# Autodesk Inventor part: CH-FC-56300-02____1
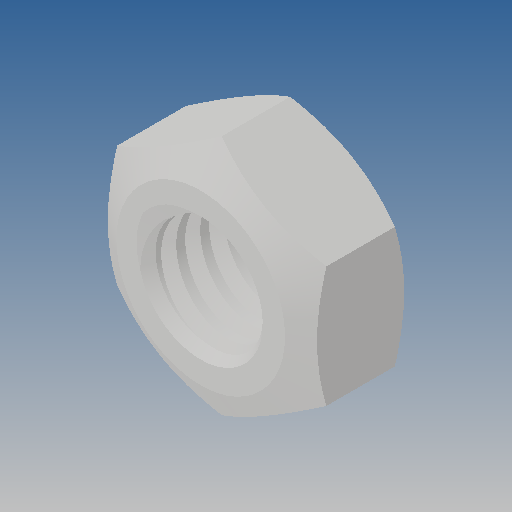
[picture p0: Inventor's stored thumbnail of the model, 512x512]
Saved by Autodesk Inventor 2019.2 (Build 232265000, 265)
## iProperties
Created: 2012-09
Part Number: CH-FC-56300-02____1
Material: Ogólny
Document SubType Name: Modeling
Designer: CADENGINEERING4
Density: 1 g/cm^3
Appearance: Domyślna
Author: CADENGINEERING4
Revision Number: ÈÎºÎ
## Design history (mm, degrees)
feature "NONE"
node "Bryła1"
